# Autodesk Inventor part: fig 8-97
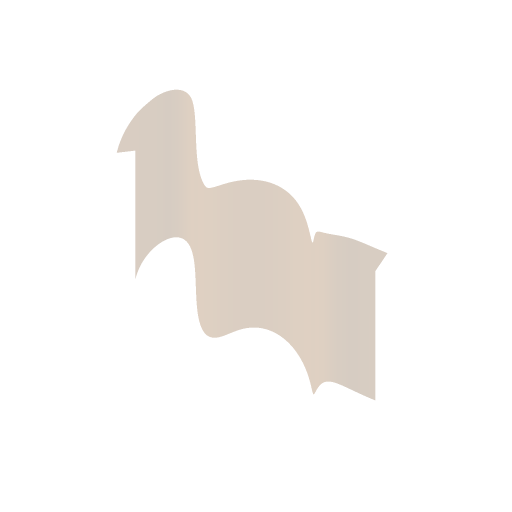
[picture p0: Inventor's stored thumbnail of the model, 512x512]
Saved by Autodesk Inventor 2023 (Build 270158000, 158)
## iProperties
Part Number: fig 8-97
Document SubType Name: Modeling
Created: 2003-08
Designer: Owner
Manufacturer: Standard
Standards Organization: Custom
Density: 1 g/cm^3
Material: Generic
Appearance: Default
Control State: 0
Master: False
Checked Out: False
Shininess: 64.0
Length Units: 11269
Angle Units: 11279
Time Units: 11290
Mass Units: 11283
Length Display Precision: 3
Angle Display Precision: 2
Compacted: True
Density: 0.0
Volumn: 0.0
Area: 0.0
PropertySet Name: Model Information
Author: Owner
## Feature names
1. Split6
## Parameters: d3 = 0, d5 = 0, d6 = 0, d8 = 0
